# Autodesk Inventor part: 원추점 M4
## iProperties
IsCustomPart: 1
Created: 2009-02
Part Number: 원추점 M4
Material: 강, 연강
Description: 6각 소켓 머리 없는 멈춤 나사
Document SubType Name: Modeling
Standard: KS B 1028
Designer: SeoGD™[esajin.kr]
Standards Organization: KS
Language: ko-KR
Size Designation: 원추점 M4x8
Categories: <MemberInstance><Categories><Category DisplayName="조임쇠" InternalName="e4da775c-781d-43d5-af7c-5136215cf5a6" Mnemonic="FSTN"><Category DisplayName="볼트" InternalN
Density: 1 g/cm^3
Author: SeoGD™[esajin.kr]
